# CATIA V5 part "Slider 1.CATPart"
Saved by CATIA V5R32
Part number: Part 2
Bounding box of the stored display mesh (mm): x 0 to 20, y -5 to 5, z -5 to 5
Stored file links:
  D:\PROJECTS\Project 2022\CATIA V5 6R 2022\Resources\Part Files\c16_catia_v5_6r2022_prt\Cable Joint - (Fig16-60)\Slider 1.CATPart
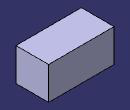
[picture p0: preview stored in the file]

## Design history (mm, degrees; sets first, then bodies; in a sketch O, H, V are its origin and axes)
Body1 (main body)
  Sketch1 on yz-plane, origin (0, 0, 0), H (0, 1, 0), V (0, 0, 1)
    line L1 (5, 5) -> (5, -5)
    line L2 (5, -5) -> (-5, -5)
    line L3 (-5, -5) -> (-5, 5)
    line L4 (-5, 5) -> (5, 5)
    length L4 = 10
    length L1 = 10
    vertical: L1 V, L3 V
    horizontal: L2 H, L4 H
    equidistance: L1 L3 O, L2 L4 O
  Pad1: profile Sketch1, direction (1, 0, 0), length 20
